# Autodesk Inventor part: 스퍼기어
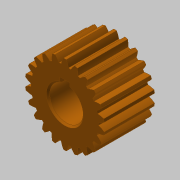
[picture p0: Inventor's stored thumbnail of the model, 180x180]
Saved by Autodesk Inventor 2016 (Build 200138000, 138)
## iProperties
Created: 2019-03
Part Number: 스퍼기어
Material: 강철
Document SubType Name: Modeling
Designer: mduedu
Categories: <?xml version="1.0" encoding="UTF-16"?> <MemberInstance><Categories><FamilyTemplate><FamilyTemplateParameter ValueType="xs:double" Id="1" ObjectReferenceKey="da
Density: 1 g/cm^3
Appearance: 주황색
CustomPartVersion: 1
Author: mduedu
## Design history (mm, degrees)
sketch "Sketch1"
  geometry: C1 r 23.6 at (0, 0)
  constraints: 1 centre point
  dimensions: "d0" = 47.2 diameter of C1 (= da_da)
extrude "Extrusion1" new body sketch "Sketch1" distance "d1" = 30 (= da_b); taper "d2" = 0 deg
workplane "Work Plane2"
sketch "Sketch2"
  geometry: C1 r 23.6 at (0, 0) reference; C2 r 22 at (0, 0)
  constraints: 1 centre point, 1 coincident
  dimensions: "d3" = 44 diameter of C2 (= da_dw)
feature "피치 지름" sketch "Sketch2" dims "d4" = 10, "d5" = 0
workplane "Work Plane8"
workplane "Work Plane9"
feature "스퍼 기어" dims "d16" = 44 (= da_aw), "da_b" = 30, "da_d" = 44, "da_aw" = 44, "da_da" = 47.2, "da_df" = 40.172, "da_dw" = 44, angle "da_beta" = 0 deg, "da_lefttooth" = 0, "da_righttooth" = 0
sketch "스케치3"
  geometry: L1 (-3, 9.539)-(3, 9.539); L2 (3, 9.539)-(3, 12.8); L3 (3, 12.8)-(-3, 12.8); L4 (-3, 12.8)-(-3, 9.539); A1 r 10 centre (0, 0) between (-3, 9.539) and (3, 9.539); 1 further point
  constraints: 8 end point, 2 parallel, 2 point on circle, 1 centre point, 1 coincident, 1 horizontal, 1 perpendicular
  dimensions: "d49" = 20 diameter of A1; "d50" = 6 distance of L2.end L3.end; "d51" = 22.8 dimension on A1 L3
extrude "돌출2" cut sketch "스케치3" stored distance "d52" = 10; taper "d53" = 0 deg
chamfer "모따기1" distance "d54" = 1; stored, may be unused: second distance "d55" = 2, angle "d56" = 45 deg
body "Solid1"
body "Srf1"
other parameters: "d17" = 0, "d34" = 1.428 (computed from da_z), "d39" = 0, "d41" = 0, "d43" = 44 (= da_aw), "d46" = 44 (= da_aw), "d47" = 0, "d48" = 0
